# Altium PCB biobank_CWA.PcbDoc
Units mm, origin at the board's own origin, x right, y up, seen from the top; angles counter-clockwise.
Board outline 25 x 17.85 mm, 4 copper layers (Top Layer, Ground plane, MidLayer1, Bottom Layer); 54 components, 67 nets, 283 pads, 127 vias.
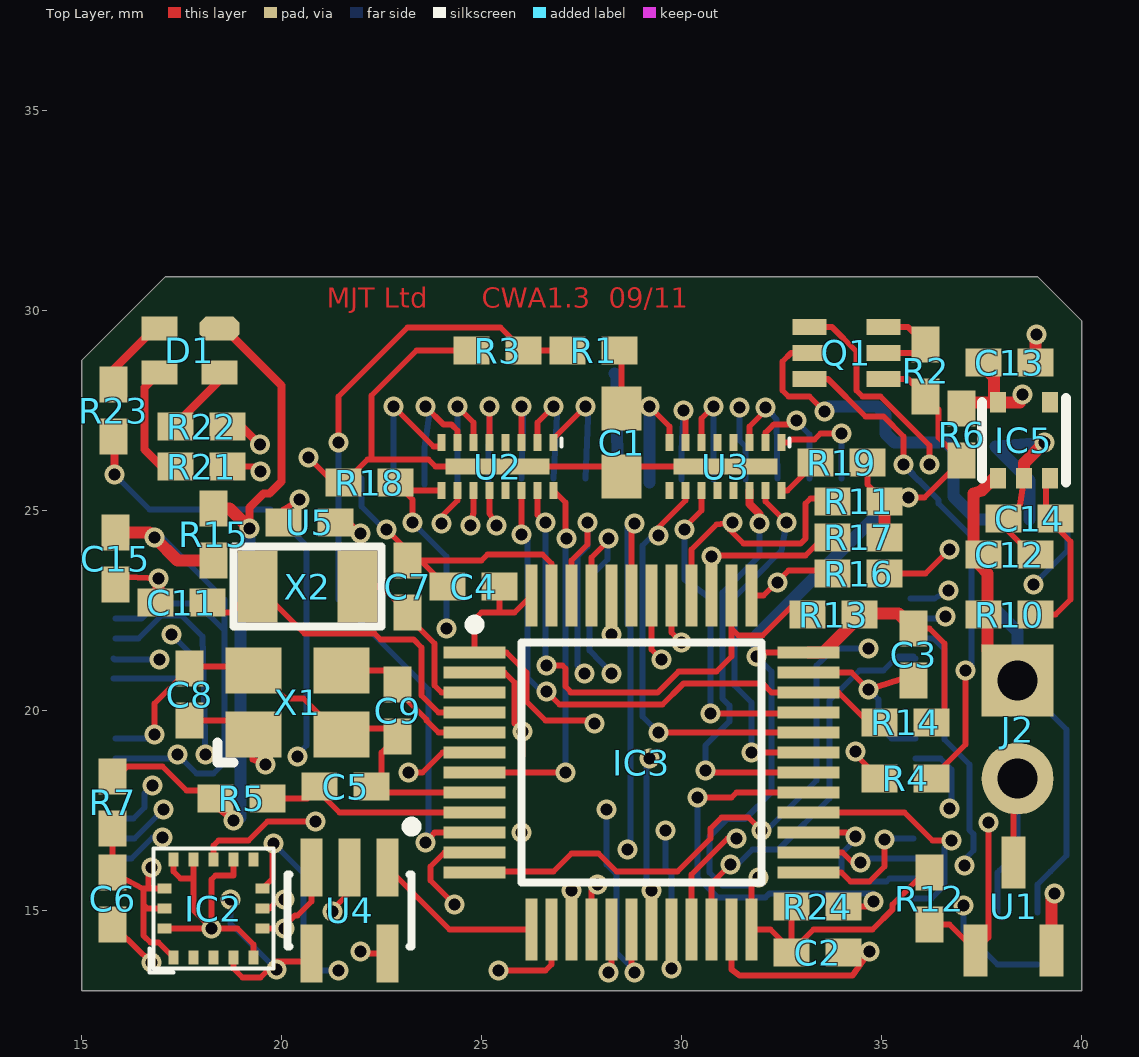
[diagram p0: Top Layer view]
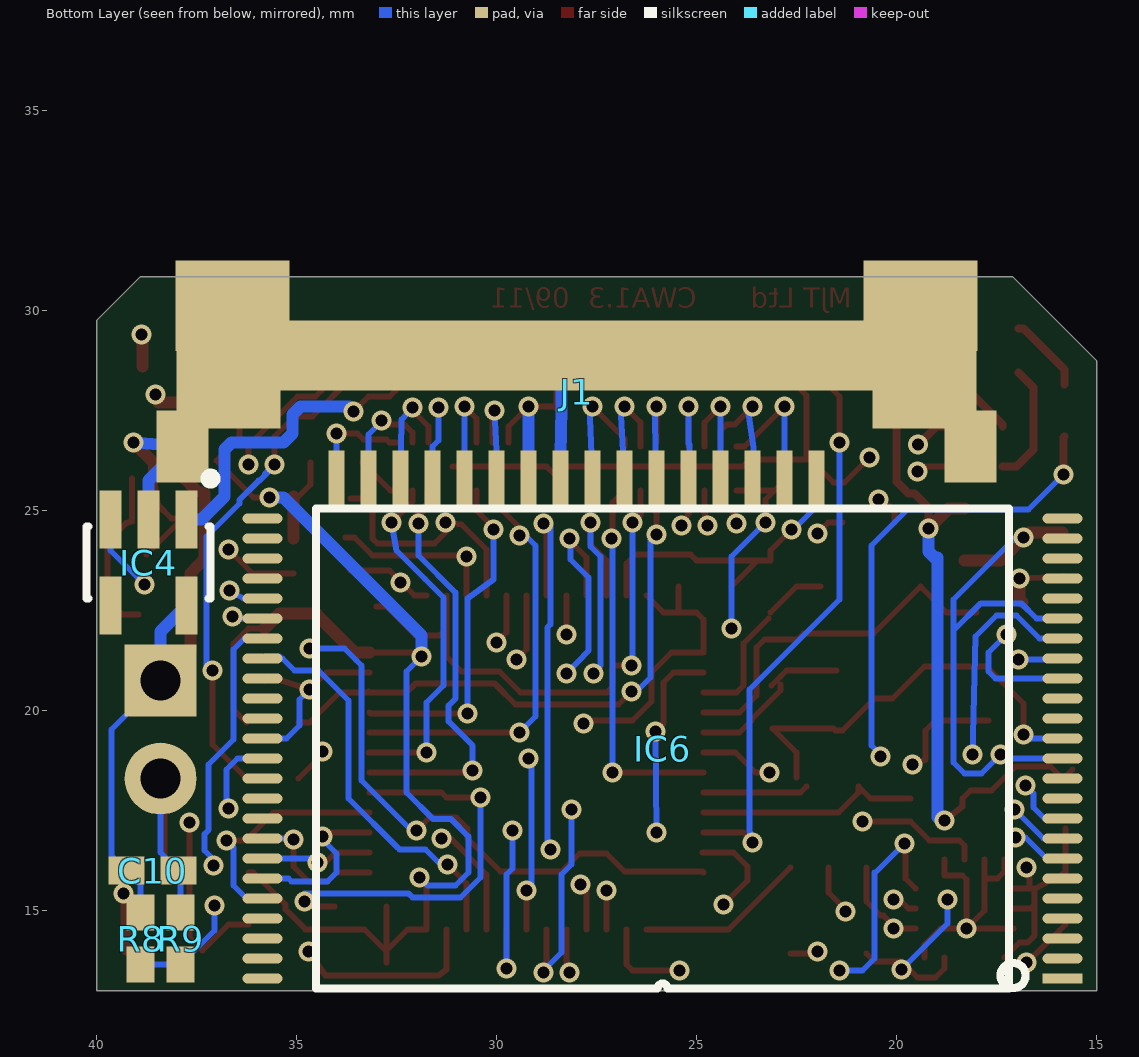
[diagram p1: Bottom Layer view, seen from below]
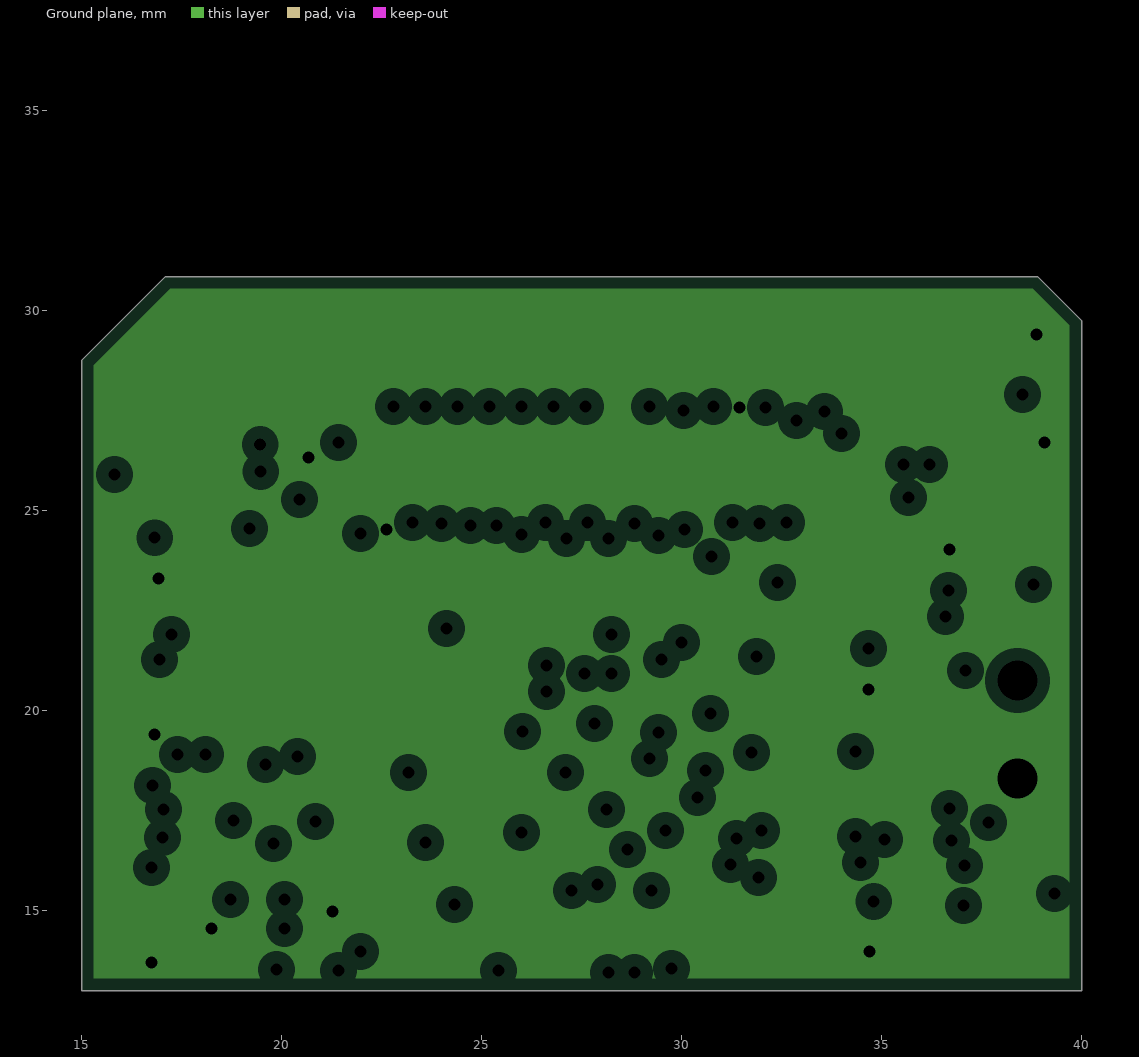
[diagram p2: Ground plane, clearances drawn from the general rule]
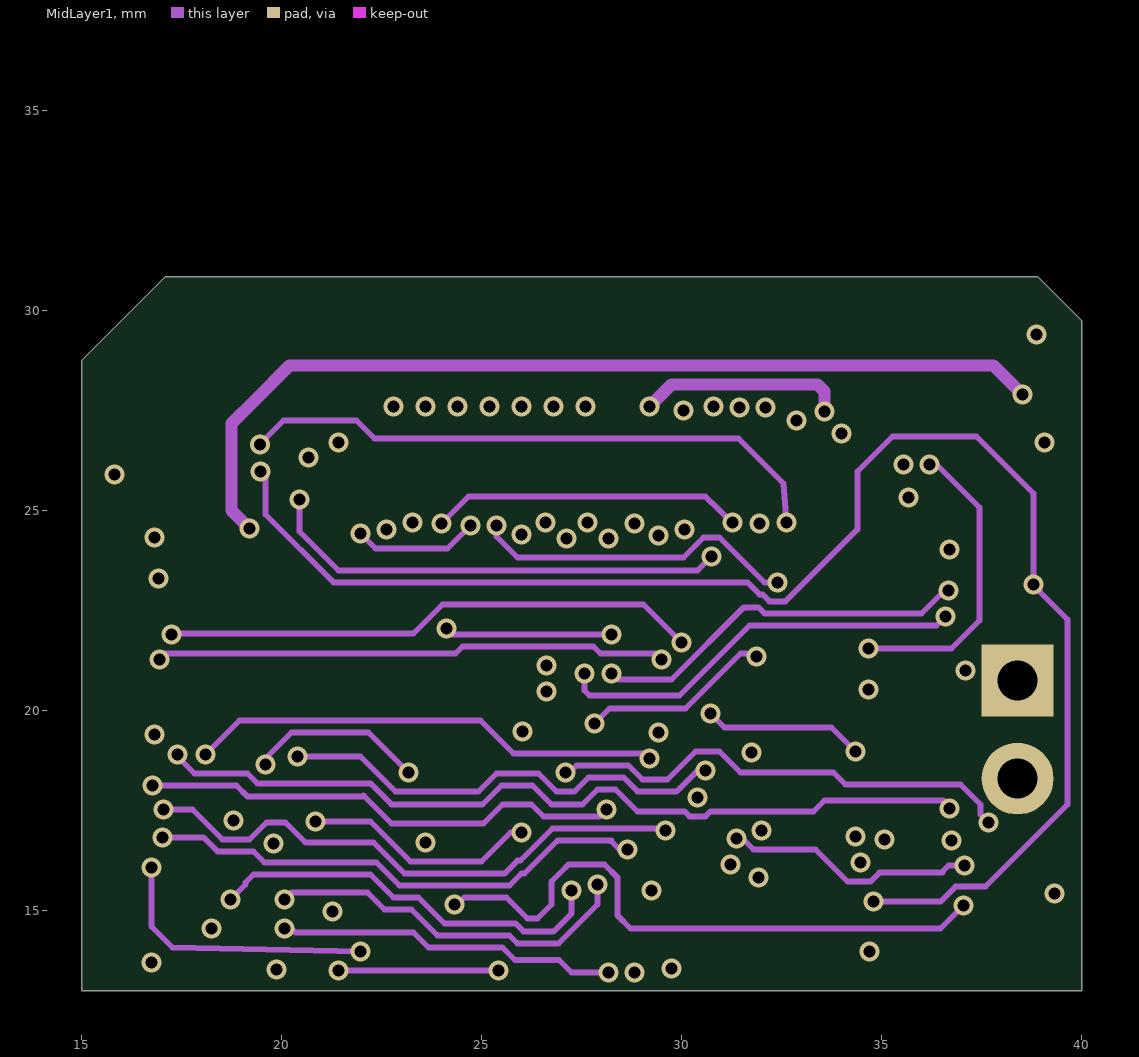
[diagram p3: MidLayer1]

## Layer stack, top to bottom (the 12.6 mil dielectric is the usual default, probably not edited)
Top Layer: signal copper 0.0356
Dielectric: core 0.32, FR-4, Dk 4.8
Ground plane: plane copper 0.0356, net GND
Dielectric: prepreg 0.32, FR-4, Dk 4.8
MidLayer1: signal copper 0.0356
Dielectric: core 0.32, FR-4, Dk 4.8
Bottom Layer: signal copper 0.0356

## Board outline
15,13 40,13 40,29.75 38.9,30.85 17.1,30.85 15,28.75

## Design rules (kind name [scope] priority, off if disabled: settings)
Clearance [All] p1: gap=0.15
ComponentClearance "Flash to socket" [(InComponent('IC6') AND InComponent('J1'))] p1: gap=-0.1 collisioncheckmode=3 verticalgap=0.254 showdistances=FALSE
ComponentClearance [All] p2: gap=0.2 collisioncheckmode=3 verticalgap=0.254 showdistances=FALSE
FabricationTestPointUsage TestPointUsage [All] p1: valid=0 allowmultiple=FALSE
FabricationTestpoint Testpoint [All] p1: side=3 testpointundercomponent=TRUE minsize=1.016 maxsize=2.54 preferedsize=1.524 minholesize=0 maxholesize=1.016 preferedholesize=0.813 testpointgrid=0.025 allowsidetop=TRUE allowsidebottom=TRUE usegrid=TRUE gridtolerance=0
PlaneClearance [All] p1: clearance=0.308
PlaneConnect [All] p1: planeconnectstyle=Relief reliefexpansion=0.508 reliefentries=4 reliefconductorwidth=0.254 reliefairgap=0.254
PolygonConnect [All] p1: connectstyle=Relief reliefconductorwidth=0.254 reliefentries=4 polygonreliefangle="90 Angle"
RoomDefinition biobank_CWA [InComponentClass('biobank_CWA')] p1: confinementstyle=ConfineIn formatcopy=TRUE lockcomponents=FALSE outline 4.75,0.5 61.75,0.5 61.75,38 4.75,38
RoutingVias [All] p1: holewidth=0.3 width=0.5 viastyle="Through Hole" minholewidth=0.3 minwidth=0.5 maxholewidth=0.3 maxwidth=0.5
SilkscreenOverComponentPads [All] p1: minsilkscreentomaskgap=0.254
SolderMaskExpansion [All] p1: expansion=0.102
Width [All] p1: maxlimit=1 minlimit=0.15 preferedwidth=0.15
22 further rules are at their usual default settings.

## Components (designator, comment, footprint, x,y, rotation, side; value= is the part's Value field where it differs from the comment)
C1 "C_0603_1u0_16V_X7R" 0603-NP 28.5,26.7 r90 top
C2 "" 0402-NP 33.4,13.95 r180 top
C3 "" 0402-NP 35.8,21.4 r90 top
C4 "" 0402-NP 24.8,23.1 r0 top
C5 "" 0402-NP 21.6,18.1 r180 top
C6 "" 0402-NP 15.775,15.3 r90 top
C7 "C_0402_4p7" 0402-NP 23.15,23.1 r270 top
C8 "C_0402_22p_NPO" 0402-NP 17.7,20.4 r270 top
C9 "C_0402_22p_NPO" 0402-NP 22.9,20 r90 top
C10 "C_0402_1u0_6V3_X5R" 0402-NP 38.6,16 r0 bottom
C11 "C_0402_4p7" 0402-NP 17.5,22.7 r0 top
C12 "" 0402-NP 38.2,23.9 r180 top
C13 "C_0402_1u0_6V3_X5R" 0402-NP 38.2,28.7 r180 top
C14 "C_0402_1u0_6V3_X5R" 0402-NP 38.7,24.8 r0 top
C15 "" 0402-NP 15.85,23.8 r90 top
D1 "" AVAGO_HSMF_C114 17.7,29 r180 top
IC2 "LIS331DLH" LGA16 18.3,15.05 r0 top
IC3 "*" F-QFP7x7-G48/N 29,18.7 r0 top
IC4 "*" SOT23-5 38.7,23.7 r0 bottom
IC5 "*" SC70 37.9,25.8 r0 top
IC6 "HY27UF084G2B-TPCB" IC_TSOPI_48_0.5MM 15.85,13.3 r0 bottom
J1 "*" HANDYLINK_16_WITH_PEGS 28,26.5 r180 bottom
J2 "CONN_2_PIN_0.1_NOOUTLINE" 2WAY_0.1_NOOUTLINE 38.4,19.5 r270 top
Q1 "FDG8842CZ" SC70-6 33.2,29.6 r270 top
R1 "" 0402-NP 27.8,29 r0 top
R2 "R_0402_10k" 0402-NP 36.1,28.5 r270 top
R3 "R_0402_220k" 0402-NP 25.4,29 r0 top
R4 "R_0402_1k5" 0402-NP 35.6,18.3 r0 top
R5 "R_0402_10R" 0402-NP 19,17.8 r180 top
R6 "R_0402_0R" 0402-NP 37,26.9 r90 top
R7 "R_0402_0R" 0402-NP 15.775,17.7 r90 top
R8 "R_0402_220k" 0402-NP 38.9,14.3 r90 bottom
R9 "" 0402-NP 37.9,14.3 r270 bottom
R10 "R_0402_10k" 0402-NP 38.2,22.4 r0 top
R11 "" 0402-NP 34.425,25.225 r0 top
R12 "" 0402-NP 36.2,15.3 r90 top
R13 "" 0402-NP 33.8,22.4 r180 top
R14 "" 0402-NP 35.6,19.7 r180 top
R15 "R_0402_0R" 0402-NP 18.3,24.4 r270 top
R16 "" 0402-NP 34.425,23.425 r180 top
R17 "" 0402-NP 34.425,24.325 r0 top
R18 "" 0402-NP 22.2,25.7 r180 top
R19 "R_0402_10k" 0402-NP 34,26.2 r0 top
R21 "R_0402_82R" 0402-NP 18,26.1 r180 top
R22 "" 0402-NP 18,27.1 r180 top
R23 "R_0402_82R" 0402-NP 15.8,27.5 r270 top
R24 "R_0402_10k" 0402-NP 33.4,15.1 r180 top
U1 "STM1001SWX6F" SOT23-3 38.3,15.1 r0 top
U2 "VEMI85AA-HGK" LLP3313-17L 25.4,26.1 r270 top
U3 "VEMI85AA-HGK" LLP3313-17L 31.1,26.1 r270 top
U4 "LM95071" SOT23-5 21.7,15 r180 top
U5 "JTAG DUMMY CORTEX M3" 0402-NP 20.7,24.7 r0 top
X1 "*" XTAL_25_32 20.4,20.2 r0 top
X2 "*" XTAL_15_32 20.65,23.1 r0 top

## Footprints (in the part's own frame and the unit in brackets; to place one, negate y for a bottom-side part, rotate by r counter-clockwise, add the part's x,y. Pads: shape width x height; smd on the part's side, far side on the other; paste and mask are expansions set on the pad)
2WAY_0.1_NOOUTLINE [mm]
  rect 1.8x1.8 hole 1: 1(-1.25,0)
  round 1.8 hole 1: 2(1.2,0)
0402-NP [mm]
  rect 0.9x0.7 smd: 1(-0.65,0) 2(0.65,0)
0603-NP [mm]
  rect 1.1x1 smd: 1(-0.85,0) 2(0.85,0)
AVAGO_HSMF_C114 [mm] "Avago HSMF-C114 multicolour LED"
  oct 1x0.6 smd: 1(-0.75,-0.55)
  rect 0.9x0.6 smd: 2(-0.75,0.55) 3(0.75,0.55) 4(0.75,-0.55)
F-QFP7x7-G48/N [mm] "QFP; 48 Leads; Body 7 x 7 mm; Pitch 0.5 mm"
  rect 1.55x0.3 smd: 1(-4.175,2.75) 2(-4.175,2.25) 3(-4.175,1.75) 4(-4.175,1.25) 5(-4.175,0.75) 6(-4.175,0.25) 7(-4.175,-0.25) 8(-4.175,-0.75) 9(-4.175,-1.25) 10(-4.175,-1.75) 11(-4.175,-2.25) 12(-4.175,-2.75) 25(4.175,-2.75) 26(4.175,-2.25) 27(4.175,-1.75) 28(4.175,-1.25) 29(4.175,-0.75) 30(4.175,-0.25) 31(4.175,0.25) 32(4.175,0.75) 33(4.175,1.25) 34(4.175,1.75) 35(4.175,2.25) 36(4.175,2.75)
  rect 0.3x1.55 smd: 13(-2.75,-4.175) 14(-2.25,-4.175) 15(-1.75,-4.175) 16(-1.25,-4.175) 17(-0.75,-4.175) 18(-0.25,-4.175) 19(0.25,-4.175) 20(0.75,-4.175) 21(1.25,-4.175) 22(1.75,-4.175) 23(2.25,-4.175) 24(2.75,-4.175) 37(2.75,4.175) 38(2.25,4.175) 39(1.75,4.175) 40(1.25,4.175) 41(0.75,4.175) 42(0.25,4.175) 43(-0.25,4.175) 44(-0.75,4.175) 45(-1.25,4.175) 46(-1.75,4.175) 47(-2.25,4.175) 48(-2.75,4.175)
  silkscreen extent -4.3,-3 3,3.57
HANDYLINK_16_WITH_PEGS [mm]
  rect 0.4x1.4 smd: 1(-6,-0.7) 2(-5.2,-0.7) 3(-4.4,-0.7) 4(-3.6,-0.7) 5(-2.8,-0.7) 6(-2,-0.7) 7(-1.2,-0.7) 8(-0.4,-0.7) 9(0.4,-0.7) 10(1.2,-0.7) 11(2,-0.7) 12(2.8,-0.7) 13(3.6,-0.7) 14(4.4,-0.7) 15(5.2,-0.7) 16(6,-0.7)
  rect 14.8x1.75 smd: PAD1(0,2.375)
  rect 2.6x2.95 smd: PAD2(-8.7,2.025) PAD4(8.7,2.025)
  rect 1.3x1.8 smd: PAD3(-9.85,0.1) PAD5(9.85,0.1)
  rect 2.85x2.26 smd: TAG1(-8.6,3.62) TAG2(8.6,3.62)
IC_TSOPI_48_0.5MM [mm]
  rect 1x0.25 smd: 1(0,0)
  oval 1x0.25 smd: 2(0,-0.5) 3(0,-1) 4(0,-1.5) 5(0,-2) 6(0,-2.5) 7(0,-3) 8(0,-3.5) 9(0,-4) 10(0,-4.5) 11(0,-5) 12(0,-5.5) 13(0,-6) 14(0,-6.5) 15(0,-7) 16(0,-7.5) 17(0,-8) 18(0,-8.5) 19(0,-9) 20(0,-9.5) 21(0,-10) 22(0,-10.5) 23(0,-11) 24(0,-11.5) 25(20,-11.5) 26(20,-11) 27(20,-10.5) 28(20,-10) 29(20,-9.5) 30(20,-9) 31(20,-8.5) 32(20,-8) 33(20,-7.5) 34(20,-7) 35(20,-6.5) 36(20,-6) 37(20,-5.5) 38(20,-5) 39(20,-4.5) 40(20,-4) 41(20,-3.5) 42(20,-3) 43(20,-2.5) 44(20,-2) 45(20,-1.5) 46(20,-1) 47(20,-0.5) 48(20,0)
  silkscreen extent 0.92,-11.75 18.66,0.25
LGA16 [mm] "LGA16 for ST Accelerometers"
  rect 0.25x0.35 smd: 1(-1,-1.225) 2(-0.5,-1.225) 3(0,-1.225) 4(0.5,-1.225) 5(1,-1.225) 9(1,1.225) 10(0.5,1.225) 11(0,1.225) 12(-0.5,1.225) 13(-1,1.225)
  rect 0.35x0.25 smd: 6(1.225,-0.5) 7(1.225,0) 8(1.225,0.5) 14(-1.225,0.5) 15(-1.225,0) 16(-1.225,-0.5)
  silkscreen extent -1.6,-1.6 1.5,1.5
LLP3313-17L [mm]
  rect 0.42x0.2 smd: 1(-0.6,1.4) 2(-0.6,1) 3(-0.6,0.6) 4(-0.6,0.2) 5(-0.6,-0.2) 6(-0.6,-0.6) 7(-0.6,-1) 8(-0.6,-1.4) 9(0.6,-1.4) 10(0.6,-1) 11(0.6,-0.6) 12(0.6,-0.2) 13(0.6,0.2) 14(0.6,0.6) 15(0.6,1) 16(0.6,1.4)
  rect 0.4x2.6 smd: 17(0,0)
  silkscreen extent -0.7,1.6 -0.5,1.6
SC70 [mm]
  rect 0.41x0.51 smd: 1(0.011,0.006) 2(0.661,0.006) 3(1.311,0.006) 4(1.311,1.906) 5(0.011,1.906)
  silkscreen extent -0.39,-0.09 1.71,2.01
SC70-6 [mm]
  rect 0.4x0.85 smd: 1(0.009,-0.005) 2(0.659,-0.005) 3(1.309,-0.005) 4(1.309,1.845) 5(0.659,1.845) 6(0.009,1.845)
SOT23-3 [mm] "SOT-23; 3 Leads; Body 3.0 x 2.6 mm, inc. leads (LxW max)"
  rect 0.6x1.3 smd: 1(-0.95,-1.1) 2(0.95,-1.1) 3(0,1.1)
SOT23-5 [mm] "SOT-23/SC-74A; 5 Leads; Body 3.1 x 3 mm, inc. leads (LxW max)"
  rect 0.55x1.45 smd: 1(-0.95,-1.075) 2(0,-1.075) 3(0.95,-1.075) 4(0.95,1.075) 5(-0.95,1.075)
  silkscreen extent -1.67,-2.22 1.55,0.9
XTAL_15_32 [mm]
  rect 1x1.8 smd: 1(-1.25,0) 2(1.25,0)
  silkscreen extent -1.85,-1 1.85,1
XTAL_25_32 [mm]
  rect 1.4x1.15 smd: 1(-1.1,-0.8) 2(1.1,-0.8) 3(1.1,0.8) 4(-1.1,0.8)
  silkscreen extent -2,-1.5 -1.6,-1

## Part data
C1 C7 C8 C9 C10 C11 C13 C14: "Capacitor"
C2 C3 C4 C5 C6 C12 C15: library part C_0402_100n_X7R, "Capacitor"
D1: library part HSMF-C114, "Avago HSMF-C114 RGB LED"
IC2: "ST digital accelerometer"
IC3: library part STM32F103C6T6, "STM32F103C6T6"
IC4: library part MAX1555EZK, "LiIon USB battery charger"
IC5: library part ZXCL280H5TA, "SC70 LDO 2.8V Regulator"
IC6: "Hynix 4Gbit NAND Flash"
J1: library part CONN_HANDYLINK_16_0.8_MOLEX_WITH_PEGS, "Molex Handylink 16 way 0.8mm"
J2: "2 pin 0.1in header"
R1 R9 R11 R12 R13 R14 R16 R17 R18: library part R_0402_100k, "Resistor"
R2 R3 R4 R5 R6 R7 R8 R10 R15 R19 R21 R23 R24: "Resistor"
R22: library part R_0402_150R, "Resistor"
U1: "Reset supervisor 2.93V open drain"
U2 U3: "8-way ESD protection"
U4: "Temperature sensor"
U5: library part JTAG_DUMMY_CORTEX_M3, "Dummy device so XJTAG is happy with number of devices in chain"
X1: library part XTAL_C3E_16MHz, "16MHz crystal 2.5x3,2mm"
X2: library part XTAL_15_32_32.768kHz_9pF, "32.768kHz 1.5x3.2mm 9pF load"

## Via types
v1: diameter 0.5, hole 0.3, Top Layer to Bottom Layer, 127 vias

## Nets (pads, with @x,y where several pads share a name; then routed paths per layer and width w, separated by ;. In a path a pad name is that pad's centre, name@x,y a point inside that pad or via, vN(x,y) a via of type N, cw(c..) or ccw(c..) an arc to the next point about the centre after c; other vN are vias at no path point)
ACC_INT: IC2.11 IC3.2 | length 14
  Top Layer w0.15: IC2.11 18.3,16.625 18.425,16.75 19.175,16.75 19.65,17.225 v1(20.85,17.225) v1@20.9,17.175 ; IC3.2 25.575,20.95 25.825,20.7 25.825,19.675 v1(26.025,19.475)
  MidLayer1 w0.15: v1(20.85,17.225) 22.225,17.225 23.225,16.225 25,16.225 25.725,16.95 v1(26,16.95)
  Bottom Layer w0.15: v1(26,16.95) v1(26.025,19.475)
BATT_SAMPLE: IC3.11 R8.1 R9.2 | length 20.7
  Top Layer w0.15: v1(24.325,15.15) 23.725,15.75 23.725,16.1 24.075,16.45 IC3.11 IC3.11@24.85,16.45
  MidLayer1 w0.15: v1(24.325,15.15) 24.4,15.15 24.575,15.325 25.625,15.325 26.15,14.8 26.4,14.8 26.75,15.15 26.75,15.726 27.124,16.1 ; 27.1,16.075 27.175,16.15 28.075,16.15 28.396,15.829 28.396,14.879 28.725,14.55 36.475,14.55 v1(37.05,15.125)
  Bottom Layer w0.15: v1(37.05,15.125) 37.05,14.5 R9.2 R8.1
BOOT0: IC3.44 R18.1 U2.9 | length 10.4
  Top Layer w0.15: R18.1@22.825,25.65 22.825,25.725 23.275,25.275 v1(23.275,24.7) ; R18.1@23.05,25.5 U2.9 ; v1(28.25,21.9) IC3.44
  MidLayer1 w0.15: v1(24.125,22.05) 24.275,21.9 v1(28.25,21.9)
  Bottom Layer w0.15: v1(23.275,24.7) 24.125,23.85 v1(24.125,22.05)
BOOT0_EXT: J1.15 U2.8 | length 3.5
  Top Layer w0.15: v1(22.8,27.6) 23.8,26.6 U2.8@24,26.6
  Bottom Layer w0.15: J1.15@22.8,25.725 22.8,26.525 v1(22.8,27.6)
CPU_TDO: IC3.39 R17.1 U5.1 | length 16.7
  Top Layer w0.15: U5.1 20.05,25.025 v1(20.45,25.275) ; IC3.39 v1(30.75,23.85) ; v1@30.75,23.7 30.925,23.875 33.1,23.875 33.55,24.325 R17.1
  MidLayer1 w0.15: v1(20.45,25.275) 20.45,24.475 21.425,23.5 30.4,23.5 v1(30.75,23.85)
D+EXT: J1.5 U3.6 | length 2.8
  Top Layer w0.15: U3.6 30.5,27.3 v1(30.8,27.6)
  Bottom Layer w0.15: J1.5@30.8,25.775 v1(30.8,27.6)
D+INT: IC3.33 R4.1 U3.11 | length 13.5
  Top Layer w0.15: v1(30.075,24.525) 30.2,24.7 30.5,25 U3.11 ; v1(30.725,19.925) 33.15,19.925 IC3.33 ; v1(34.35,18.975) 34.35,18.9 R4.1
  MidLayer1 w0.15: v1(30.725,19.925) 31.075,19.575 33.75,19.575 v1(34.35,18.975)
  Bottom Layer w0.15: v1(30.075,24.525) 30.075,23.275 30.725,22.8 v1(30.725,19.925)
D-EXT: J1.6 U3.7 | length 2.7
  Top Layer w0.15: v1(30.05,27.5) 30.1,27.5 U3.7
  Bottom Layer w0.15: J1.6@30,25.775 30,26.5 30.05,27.475 v1(30.05,27.5) v1@30,27.6
D-INT: IC3.32 U3.10 | length 10.7
  Top Layer w0.15: v1(29.425,19.45) 29.925,19.45 IC3.32 ; v1(29.425,24.375) 29.425,24.575 30.1,25.25 U3.10
  Bottom Layer w0.15: v1(29.425,19.45) 29.025,19.85 29.025,24.125 29.425,24.525 v1(29.425,24.375)
GND: C1.1 C2.1 C3.1 C4.1 C5.1 C6.1 C7.1 C8.1 C9.1 C10.1 C11.1 C12.1 C13.1 C14.1 C15.1 IC2.5 IC2.10 IC2.12 IC2.13 IC2.16 IC3.8 IC3.23 IC3.35 IC3.47 IC4.2 IC5.2 IC6.13 IC6.36 J1.4 J1.8 J1.16 J1.PAD1 J1.PAD2 J1.PAD3 J1.PAD4 J1.PAD5 J1.TAG1 J1.TAG2 J2.2 R3.1 R9.1 R16.1 R18.2 U1.3 U2.17 U3.17 U4.2 X1.2 X1.4 | length 79.5
  Top Layer w0.15: C6.1 15.925,14.5 v1(16.75,13.7) ; C15.1@15.8,23.35 15.859,23.347 v1(16.925,23.3) ; v1(16.825,19.4) 16.825,20.175 C8.1 ; IC2.16 18.9,14.55 19.3,14.15 IC2.5 ; IC2.13 17.3,15.975 17.475,15.8 17.8,15.8 ; C8.1@17.75,21.1 19.3,21.1 20.1,20.3 20.55,20.3 21.35,19.5 21.525,19.5 21.575,19.55 C9.1@23.1,19.55 ; IC2.12 17.8,15 v1(18.25,14.55) 18.25,15.775 18.35,15.875 18.775,15.875 ; 18.8,15.875 IC2.10 ; v1(20.675,26.325) 21.3,25.7 21.575,25.7 22.15,26.275 23.675,26.275 23.85,26.1 U2.17 28.25,26.1 C1.1 28.75,26.1 U3.17 ; v1@21.225,14.975 21.7,15.45 U4.2 ; C5.1 22.4,17.95 IC3.8 ; 22.25,26.275 22.25,27.875 23.375,29 R3.1 ; C5.1@22.5,18.325 22.5,18.95 C9.1@23.1,19.55 ; v1@22.625,24.625 v1(22.625,24.525) 23.15,24 C7.1 C7.1@23.475,23.75 ; C9.1@22.9,19.55 C9.1@23.1,19.55 ; C4.1@24.125,23.1 C7.1@23.475,23.75 ; IC3.47 26.75,23.675 26.525,23.9 25.15,23.9 25,23.75 C7.1@23.475,23.75 ; IC3.23 31.25,13.525 31.45,13.375 34.275,13.375 v1(34.7,13.975) ; IC3.35 34.25,20.95 v1(34.675,20.525) 35.7,20.85 C3.1 ; R16.1 36.1,23.425 v1(36.7,24.025) ; U1.3 38.3,18.2 J2.2@38.375,18.275 ; IC5.2@38.561,25.781 38.461,25.136 38.125,24.8 37.85,24.8 C12.1@38.75,23.9
  Top Layer w0.3: C11.1 16.925,22.775 v1(16.925,23.3) ; IC5.2 38.561,26.186 v1(39.075,26.7) ; C13.1@38.85,28.6 38.85,29.375 v1(38.875,29.4)
  Bottom Layer w0.15: IC6.13 16.725,19.3 v1(16.825,19.4) ; J1.16 22,25.1 22.575,24.525 v1(22.625,24.525) ; v1(31.45,27.575) 31.454,27.576 v1@31.6,27.6 ; v1@31.45,27.6 31.45,26.75 31.6,26.6 J1.4@31.6,25.775 ; v1(34.675,20.525) 34.925,20.275 34.925,19.625 35.25,19.3 IC6.36 ; R9.1 37.9,15.95 C10.1 38.4,16.45 J2.2
  Bottom Layer w0.3: J1.PAD1@28.325,28.425 28.375,28.375 28.375,27.55 28.4,26.4 J1.8@28.4,25.675 ; J1.PAD1@28.4,28.925 J1.PAD1@28.425,28.95 ; IC4.2 38.7,25.75 J1.PAD3 v1(39.075,26.7)
  other v1: 21.275,14.975
LED_B_TXD: IC3.30 R23.2 U3.14 | length 33.7
  Top Layer w0.15: v1(30.6,18.5) 30.65,18.45 IC3.30
  Top Layer w0.2: R23.2 15.825,26.825 v1(15.825,25.9) ; U3.14 31.7,25.165 31.952,24.914 v1(31.952,24.676)
  MidLayer1 w0.15: v1(20.4,18.85) 21.975,18.85 22.85,17.975 24.925,17.975 25.375,18.425 26.425,18.425 26.875,17.975 27.325,17.975 27.675,18.325 28.551,18.325 28.901,17.975 29.878,17.975 30.403,18.5 v1(30.6,18.5)
  Bottom Layer w0.15: v1(15.825,25.9) 16.7,25.025 19.725,25.025 20.625,24.125 20.625,19.125 v1@20.4,18.9 ; v1(30.6,18.5) 30.6,19.128 31.2,19.728 31.2,20.122 31.025,20.297 31.025,22.949 31.952,23.876 v1(31.952,24.676)
  Bottom Layer w0.2: v1(31.952,24.676) v1@31.974,24.676
LED_G_NCHG: IC3.29 IC4.3 R21.1 R24.1 | length 52.5
  Top Layer w0.15: R21.1 19.352,26.1 v1(19.476,25.976) ; v1(30.4,17.825) 31.25,17.825 31.375,17.95 IC3.29 ; R24.1 34.676,15.1 v1(34.802,15.226)
  MidLayer1 w0.15: v1(19.476,25.976) 19.599,25.976 19.599,24.902 21.301,23.2 31.651,23.2 31.951,22.9 32.028,22.9 32.203,22.725 32.597,22.725 34.4,24.528 34.4,25.975 35.275,26.85 37.375,26.85 38.8,25.425 v1(38.8,23.15) 38.8,23.125 39.65,22.275 39.65,17.65 37.6,15.6 36.853,15.6 36.479,15.226 v1(34.802,15.226)
  Bottom Layer w0.15: v1(30.4,17.825) 30.4,15.826 30.901,15.325 32.097,15.325 32.195,15.423 34.802,15.423 v1(34.802,15.226) ; v1(38.8,23.15) 39.65,24 IC4.3 IC4.3@39.65,24.075
LED_R_RXD: IC3.31 R22.1 U3.15 | length 24.9
  Top Layer w0.15: v1(31.75,18.95) IC3.31@33.2,18.95 ; U3.15 32.1,25.225 32.575,24.75 v1(32.625,24.7)
  Top Layer w0.2: R22.1 19,27.1 19.45,26.65 v1(19.466,26.65)
  MidLayer1 w0.15: v1(19.466,26.65) 19.45,26.65 20.05,27.25 21.875,27.25 22.325,26.8 31.425,26.8 32.55,25.675 v1(32.625,24.7)
  Bottom Layer w0.15: v1(31.75,18.95) 31.75,20.2 31.325,20.625 31.325,22.825 31.788,23.288 32.5,24 v1(32.625,24.7)
NAND_ALE: IC3.42 IC6.17 | length 15.8
  Top Layer w0.15: IC3.42 29.25,21.525 v1(29.5,21.275)
  MidLayer1 w0.15: v1(16.95,21.275) 16.925,21.425 24.35,21.425 24.525,21.6 27.8,21.6 27.975,21.425 29.35,21.425 v1(29.5,21.275)
  Bottom Layer w0.15: IC6.17@15.8,21.3 15.825,21.275 v1(16.95,21.275)
NAND_CLE: IC3.41 IC6.16 | length 17.8
  Top Layer w0.15: IC3.41 29.75,21.95 v1(30,21.7)
  MidLayer1 w0.15: v1(17.25,21.9) 17.275,21.925 23.3,21.925 24.025,22.65 29.05,22.65 v1(30,21.7)
  Bottom Layer w0.15: IC6.16@15.8,20.8 17.525,20.8 17.7,20.975 17.7,21.45 v1(17.25,21.9)
NAND_D0: IC3.45 IC6.29 | length 16
  Top Layer w0.15: IC3.45 27.75,23.826 v1@28.175,24.251
  MidLayer1 w0.15: v1@28.262,20.938 28.425,20.775 29.75,20.775 31.556,22.581 31.923,22.581 32.079,22.425 36,22.425 v1@36.725,23.15
  Bottom Layer w0.15: v1@28.15,24.275 28.15,23.775 27.7,23.325 27.7,21.5 v1(28.25,20.925) ; IC6.29@35.725,22.8 36.325,22.8 v1(36.675,23)
  other v1: 28.175,24.3
NAND_D1: IC3.46 IC6.30 | length 17.4
  Top Layer w0.15: IC3.46 27.25,23.75 27.65,24.15 v1(27.65,24.7)
  MidLayer1 w0.15: v1(27.575,20.925) 27.575,20.5 27.7,20.375 29.95,20.375 31.7,22.125 36.375,22.125 v1@36.531,22.281 ; v1@36.481,22.331 36.5,22.35 v1(36.6,22.35)
  Bottom Layer w0.15: v1(27.575,20.925) 27.4,21.125 27.4,23.85 27.65,24.1 v1(27.65,24.7) ; IC6.30@35.8,22.3 36.75,22.3 v1(36.6,22.35)
NAND_D2: IC3.21 IC6.31 | length 15.9
  Top Layer w0.15: IC3.21 30.25,15.901 31.149,16.8 v1(31.375,16.8)
  MidLayer1 w0.15: v1(31.375,16.8) 31.525,16.8 31.8,16.525 33.35,16.525 34.15,15.725 34.726,15.725 34.951,15.95 36.525,15.95 ; 36.5,15.95 36.675,16.125 v1(37.075,16.125)
  Bottom Layer w0.15: IC6.31@35.8,21.8 36.3,21.8 36.575,21.525 36.575,19.275 37.2,18.65 37.2,17.008 37.3,16.908 37.3,16.5 37.075,16.275 v1(37.075,16.125)
NAND_D3: IC3.22 IC6.32 | length 10.4
  Top Layer w0.15: IC3.22 30.75,15.675 v1(31.225,16.15)
  Bottom Layer w0.15: v1(31.225,16.15) 31.4,16.15 31.775,16.525 32.425,16.525 ; 32.425,16.525 32.482,16.582 33.7,17.8 33.7,20.25 34.45,21 35.05,21 35.35,21.3 IC6.32 ; IC6.32@35.425,21.35 IC6.32@35.8,21.35
NAND_D4: IC3.25 IC6.41 | length 3.9
  Top Layer w0.15: IC3.25 34,15.95 34.225,15.725 34.7,15.725 35.075,16.1 v1(35.075,16.775)
  Bottom Layer w0.15: v1(35.075,16.775) 34.925,16.8 IC6.41@35.8,16.8
NAND_D5: IC3.26 IC6.42 | length 2.8
  Top Layer w0.15: IC3.26 34.025,16.45 34.275,16.2 v1(34.475,16.2)
  Bottom Layer w0.15: v1(34.475,16.2) 34.575,16.3 IC6.42
NAND_D6: IC3.27 IC6.43 | length 4.2
  Top Layer w0.15: IC3.27@33.2,16.95 IC3.27 34.125,16.95 v1(34.35,16.85)
  Bottom Layer w0.15: v1(34.35,16.85) 34.35,16.775 34,16.425 34,15.95 34.225,15.725 35.125,15.725 35.2,15.8 IC6.43
NAND_D7: IC3.28 IC6.44 | length 6
  Top Layer w0.15: IC3.28 35.575,17.45 36.275,16.75 v1(36.75,16.75)
  Bottom Layer w0.15: IC6.44@35.8,15.3 36.25,15.3 36.575,15.625 36.575,16.575 v1(36.75,16.75)
NAND_NCE: IC3.18 IC6.9 | length 18.8
  Top Layer w0.15: v1@28.75,13.575 IC3.18
  MidLayer1 w0.15: v1(16.775,18.125) 18.875,18.125 19.143,17.857 22.068,17.857 ; 22.05,17.875 22.75,17.175 25.05,17.175 25.525,17.65 26.25,17.65 26.55,17.35 27.95,17.35 v1(28.125,17.525)
  Bottom Layer w0.15: IC6.9 16.3,17.3 16.575,17.575 16.575,17.925 v1(16.775,18.125) ; v1@28.125,17.475 28.125,16.15 28.375,15.9 28.375,13.95 v1@28.825,13.5
  other v1: 28.825,13.45
NAND_NRE: IC3.20 IC6.8 | length 20.1
  Top Layer w0.15: v1(29.75,13.55) IC3.20
  MidLayer1 w0.15: v1(17.05,17.525) 17.775,17.525 18.525,16.775 19.2,16.775 19.625,17.2 20.1,17.2 20.6,16.7 22.3,16.7 23.075,15.925 25.576,15.925 25.901,16.25 25.974,16.25 26.774,17.05 v1@29.6,17.05
  Bottom Layer w0.15: IC6.8 16.325,16.8 v1(17.05,17.525) ; v1@29.6,17.05 29.6,16.05 29.75,15.9 v1(29.75,13.55)
  other v1: 29.6,17
NAND_NWE: IC3.19 IC6.18 | length 21.9
  Top Layer w0.15: IC3.19 v1(29.25,15.5)
  MidLayer1 w0.15: v1(18.1,18.9) 18.95,19.75 24.975,19.75 25.8,18.925 29.075,18.925 v1(29.2,18.8)
  Bottom Layer w0.15: IC6.18 16.425,21.8 17,22.375 17.5,22.375 18.025,21.85 v1(18.1,18.9) ; v1(29.25,15.5) 29.125,15.625 29.125,18.725 v1(29.2,18.8) 29.25,18.825 v1@29.25,18.8
NAND_RNB: IC3.43 IC6.7 | length 24.2
  Top Layer w0.15: IC3.43 v1@28.75,24.675
  MidLayer1 w0.15: v1(17.025,16.825) 18.051,16.825 18.401,16.475 19.3,16.475 19.575,16.2 22.375,16.2 22.95,15.625 25.7,15.625 26,15.925 26.073,15.925 26.898,16.75 28.25,16.75 28.25,16.725 28.45,16.525 v1(28.65,16.525)
  Bottom Layer w0.15: IC6.7 16.25,16.3 16.775,16.825 v1(17.025,16.825) ; v1(28.65,16.525) 28.725,16.6 28.725,22.081 28.65,22.156 28.65,24.6 v1(28.825,24.675)
NetC14_2: C14.2 IC5.3 R10.2 | length 4.2
  Top Layer w0.15: R10.2@38.95,22.4 39.35,22.4 39.725,22.775 39.725,24.225 39.261,24.689 C14.2@39.111,24.725 ; C14.2@39.111,24.8 IC5.3@39.111,25.806
NetD1_2: D1.2 R22.2 | length 1.8
  Top Layer w0.2: R22.2 17.35,27.15 18.45,28.25 D1.2
NetD1_3: D1.3 R21.2 | length 3
  Top Layer w0.2: D1.3 16.575,28.075 16.575,26.525 17,26.1 R21.2
NetD1_4: D1.4 R23.1 | length 1.9
  Top Layer w0.2: R23.1 15.8,28.525 16.825,29.55 D1.4
NetQ1_3: Q1.3 R4.2 | length 12.7
  Top Layer w0.15: Q1.3 33.659,28.291 34.6,27.35 35.051,27.35 35.55,26.851 v1(35.55,26.15) ; R4.2 37.1,19.15 v1(37.1,21)
  Bottom Layer w0.15: v1(35.55,26.15) 35.79,25.91 35.79,25.885 ; 35.714,25.961 35.926,25.749 35.946,25.749 36.425,25.269 36.425,25.175 37.25,24.35 37.25,21.15 v1(37.1,21)
NetQ1_5: Q1.5 Q1.6 R2.1 | length 2.7
  Top Layer w0.15: Q1.5 35.891,28.941 R2.1 ; Q1.6 35.659,29.591 R2.1 ; R2.1@35.859,29.391 R2.1
NetR19_1: R19.1 U3.16 | length 1.1
  Top Layer w0.15: U3.16 32.65,25.5 R19.1
NRST: IC3.7 R12.1 U1.1 U2.16 | length 26.2
  Top Layer w0.15: IC3.7 v1(27.1,18.45) ; U2.16 27.1,25.2 v1@27.1,24.3 ; R12.1 36.7,14.65 U1.1 37.675,14.325 v1(37.675,17.2)
  MidLayer1 w0.15: v1(27.1,18.45) 27.2,18.45 27.375,18.625 28.675,18.625 29.025,18.275 29.65,18.275 30.35,18.975 30.95,18.975 31.475,18.45 33.8,18.45 34.1,18.15 36.975,18.15 37.475,17.65 37.475,17.4 v1(37.675,17.2)
  Bottom Layer w0.15: v1(27.1,18.45) v1@27.1,24.3
  other v1: 27.125,24.3
NRST_EXT: J1.9 U2.1 | length 3.2
  Top Layer w0.15: U2.1@26.8,26.6 26.8,26.8 v1(27.6,27.6)
  Bottom Layer w0.15: J1.9 27.675,27.6 v1(27.6,27.6)
NUSB_PULLUP: IC3.12 Q1.1 | length 27.5
  Top Layer w0.15: IC3.12 24.85,15.975 26.8,15.975 27.25,16.425 27.925,16.425 28.375,15.975 29.9,15.975 30.725,16.8 30.725,17.05 31,17.325 31.675,17.325 v1(32,17) ; Q1.1 33.759,29.591 34.375,28.975 34.375,28 34.525,27.85 34.975,27.85 36.2,26.625 v1(36.2,26.15)
  MidLayer1 w0.15: v1(34.675,21.55) 36.75,21.55 37.45,22.25 37.45,25.075 36.375,26.15 v1(36.2,26.15)
  Bottom Layer w0.15: v1(32,17) 32.125,17 33.375,18.25 33.375,21.125 33.513,21.263 33.8,21.55 v1(34.675,21.55)
OSC32_IN: C7.2 IC3.3 X2.2 | length 4.5
  Top Layer w0.15: X2.2 22.5,23.1 C7.2 ; C7.2@23.2,22.3 23.825,21.675 23.825,20.625 24,20.45 IC3.3
OSC32_OUT: C11.2 IC3.4 X2.1 | length 9.1
  Top Layer w0.15: C11.2@18,22.45 18.75,22.45 X2.1 20.575,21.925 22.325,21.925 22.475,21.775 23.301,21.775 23.5,21.576 23.5,20.375 23.925,19.95 IC3.4
OSC_IN: C9.2 IC3.5 X1.3 | length 4.3
  Top Layer w0.15: X1.3 22.75,21 22.9,20.85 C9.2@23.125,20.625 ; C9.2 22.9,20.5 23.625,19.775 23.625,19.75 23.925,19.45 IC3.5
OSC_OUT: C8.2 IC3.6 X1.1 | length 9
  Top Layer w0.15: C8.2 19.025,19.75 19.275,19.5 19.275,18.775 v1(19.6,18.65) ; v1(23.175,18.45) 23.525,18.45 24.025,18.95 IC3.6
  MidLayer1 w0.15: v1(19.6,18.65) 19.6,18.8 20.25,19.45 22.175,19.45 v1(23.175,18.45)
RXD_EXT: J1.2 U3.2 | length 2.5
  Top Layer w0.15: U3.2 32.1,26.951 32.289,27.139 ; 32.312,27.15 v1@32.7,27.15
  Bottom Layer w0.15: v1(32.875,27.25) 32.925,27.175 33.2,26.9 J1.2
SPI_MISO: IC2.7 IC3.16 | length 11.3
  Top Layer w0.15: IC2.7 19.7,15.05 19.925,15.275 v1(20.075,15.275) ; IC3.16 27.75,15.5 v1(27.9,15.65)
  MidLayer1 w0.15: v1@19.925,15.275 v1(20.075,15.275) 20.25,15.45 22.15,15.45 22.575,15.025 23.25,15.025 23.9,14.375 25.7,14.375 25.9,14.175 26.925,14.175 27.9,15.15 v1(27.9,15.65)
SPI_MOSI: IC2.6 IC3.17 U4.3 | length 12.2
  Top Layer w0.15: IC2.6 v1(20.075,14.55) 20.075,14.619 20.331,14.875 20.4,14.875 20.75,15.225 U4.3 ; v1@28.1,13.4 28.25,13.55 IC3.17
  MidLayer1 w0.15: v1@20.075,14.575 v1(20.075,14.55) 20.25,14.55 20.35,14.45 23.3,14.45 23.675,14.075 25.525,14.075 25.837,13.763 26.937,13.763 27.25,13.45 v1(28.175,13.45)
SPI_NSS: IC2.8 IC3.14 | length 11.7
  Top Layer w0.15: IC2.8 19.775,15.8 v1@19.775,16.7 ; v1(25.425,13.5) 26.6,13.5 26.75,13.65 IC3.14
  MidLayer1 w0.15: v1(21.425,13.5) v1(25.425,13.5)
  Bottom Layer w0.15: v1(19.8,16.675) 20.55,15.925 ; 20.55,15.95 20.55,13.8 20.85,13.5 v1(21.425,13.5)
SPI_SCK: IC2.4 IC3.15 U4.4 | length 15.9
  Top Layer w0.15: IC2.4 18.8,13.55 19.025,13.325 19.475,13.325 19.875,13.725 20.55,13.725 U4.4 ; IC3.15@27.25,14.525 v1(27.25,15.5)
  MidLayer1 w0.15: v1(18.725,15.275) 19.1,15.65 ; 19.1,15.7 19.3,15.9 22.225,15.9 22.8,15.325 23.425,15.325 24.075,14.675 25.851,14.675 26.051,14.475 26.801,14.475 27.25,14.924 v1(27.25,15.5)
  Bottom Layer w0.15: v1(18.725,15.275) 18.725,14.675 v1(19.875,13.525)
TCK: IC3.37 R16.2 U2.12 | length 11.3
  Top Layer w0.15: U2.12 25.2,24.925 v1(25.375,24.625) ; IC3.37 32.05,22.875 32.675,23.5 R16.2@33.65,23.5
  MidLayer1 w0.15: v1(25.375,24.625) 25.375,24.35 25.9,23.825 30.05,23.825 30.55,24.325 30.95,24.325 32.075,23.2 v1(32.4,23.2)
TCK_EXT: J1.12 U2.5 | length 2.9
  Top Layer w0.15: U2.5@25.2,26.6 v1(25.2,27.6)
  Bottom Layer w0.15: J1.12@25.175,25.725 25.175,26.65 25.2,26.675 v1(25.2,27.6)
TDI: IC3.38 R13.2 U2.15 | length 13.9
  Top Layer w0.15: U2.15 26.4,24.892 v1(26.6,24.7) ; v1(26.625,21.125) 27.025,21.125 27.1,21.05 27.1,20.6 27.25,20.45 ; 27.225,20.45 29.401,20.45 29.926,20.975 30.875,20.975 31.25,21.35 IC3.38 ; 31.25,22.05 31.425,21.875 32.025,21.875 32.75,22.6 R13.2@33,22.6
  Bottom Layer w0.15: v1(26.6,24.7) 26.6,21.025 v1(26.625,21.125)
TDI_EXT: J1.10 U2.2 | length 3.2
  Top Layer w0.15: U2.2@26.4,26.6 26.4,27.2 v1(26.8,27.6) v1@26.7,27.6
  Bottom Layer w0.15: J1.10 26.9,27.6 v1(26.8,27.6)
TDO: U2.11 U5.2 | length 4.8
  Top Layer w0.15: U5.2 21.7,24.7 v1(21.975,24.425) ; v1(24.725,24.625) 24.8,24.95 U2.11
  MidLayer1 w0.15: v1(21.975,24.425) 22.35,24.05 24.15,24.05 v1(24.725,24.625)
TDO_EXT: J1.13 U2.6 | length 3.3
  Top Layer w0.15: v1@24.5,27.6 v1(24.4,27.6) 24.8,27.2 U2.6@24.8,26.6
  Bottom Layer w0.15: J1.13@24.4,25.525 24.4,26.275 24.4,27.575 v1(24.4,27.6)
TEMP_NCS: IC3.13 U4.1 | length 4.2
  Top Layer w0.15: U4.1 24.2,14.525 IC3.13
TMS: IC3.34 R14.2 U2.14 | length 14.5
  Top Layer w0.15: v1(26,24.4) 26,24.625 U2.14 ; v1(26.625,20.475) 26.95,20.15 29.525,20.15 30.016,20.641 30.045,20.67 32.03,20.67 32.25,20.45 IC3.34 ; IC3.34@33.2,20.475 IC3.34 ; R14.2 34.675,19.7 33.925,20.45 IC3.34
  Bottom Layer w0.15: v1(26,24.4) 26.15,24.275 26.15,20.825 26.5,20.475 v1(26.625,20.475)
TMS_EXT: J1.11 U2.3 | length 2.8
  Top Layer w0.15: U2.3 v1(26,27.6)
  Bottom Layer w0.15: J1.11 26.05,27.6 v1(26,27.6)
TRST: IC3.40 R11.1 U2.10 | length 15
  Top Layer w0.15: v1(24,24.675) 24,24.85 24.4,25.25 U2.10 ; IC3.40 30.25,24.025 30.875,24.65 v1(31.275,24.7) 31.2,24.525 31.55,24.175 32.976,24.175 33.1,24.299 33.1,25.175 33.225,25.3 R11.1@33.65,25.3
  MidLayer1 w0.15: v1(24,24.675) 24.675,25.35 30.6,25.35 v1(31.275,24.7)
TRST_EXT: J1.14 U2.7 | length 3.6
  Top Layer w0.15: v1@23.7,27.6 v1(23.6,27.6) 24.051,27.149 24.251,27.149 24.4,27 U2.7@24.4,26.6
  Bottom Layer w0.15: J1.14@23.575,25.65 23.575,26.575 23.725,27.6 v1(23.6,27.6)
TXD_EXT: J1.3 U3.3 | length 2.9
  Top Layer w0.15: U3.3 31.7,27.1 32.1,27.5 v1(32.1,27.575)
  Bottom Layer w0.15: v1(32.1,27.575) 32.375,27.275 J1.3
V_BATT: C10.2 C12.2 IC4.5 IC5.1 J2.1 R8.2 R10.1 U1.2 | length 16
  Top Layer w0.3: IC5.1@37.811,25.806 37.505,25.5 37.3,25.425 37.3,23.8 37.65,23.425 37.65,23.4 37.65,21.5 J2.1 ; U1.2@39.25,14.025 39.25,15.35 v1(39.325,15.425)
  Bottom Layer w0.15: J2.1 39.625,19.525 39.625,16.375 39.225,15.975 38.9,15.65 R8.2
  Bottom Layer w0.3: IC4.5 38.4,21.975 J2.1
V_BUS: C1.2 IC4.1 J1.7 Q1.2 R1.2 U3.8 | length 19.4
  Top Layer w0.15: R1.2@28.5,28.95 C1.2 28.55,27.6 v1(29.2,27.6) 29.7,27.1 U3.8 ; Q1.2 32.741,28.941 32.525,28.725 32.525,28 32.675,27.85 33.2,27.85 v1(33.575,27.475)
  MidLayer1 w0.3: v1(29.2,27.6) 29.75,28.15 33.4,28.15 33.575,27.975 v1(33.575,27.475)
  Bottom Layer w0.3: J1.7@29.2,25.7 29.2,26.35 29.2,27.45 v1(29.2,27.6) ; v1(33.575,27.475) 33.575,27.5 33.675,27.6 34.9,27.6 35.1,27.4 35.1,26.925 35.325,26.7 36.625,26.7 36.8,26.525 36.8,25.35 37.375,24.775 IC4.1
VBUS_DET: IC3.10 R1.1 R3.2 | length 20.1
  Top Layer w0.15: v1(21.425,26.7) 21.425,27.85 23.15,29.575 25.475,29.575 R3.2 R1.1 ; v1(23.6,16.7) 23.825,16.95 IC3.10
  Bottom Layer w0.15: v1(21.425,26.7) 21.425,22.775 23.675,20.525 23.675,17 v1(23.6,16.7)
VDD_2V8: C13.2 D1.1 IC5.5 R5.2 R6.2 R7.2 R15.1 | length 45
  Top Layer w0.15: R7.2@15.6,18.525 R7.2 15.9,18.35 16.15,18.6 17.025,18.6 17.625,18 18.15,18 R5.2 18.35,17.6 v1(18.8,17.25)
  Top Layer w0.2: D1.1 18.575,29.55 20,28.125 20,25.725 19.7,25.425 19.55,25.425 19.2,25.075 v1(19.2,24.55)
  Top Layer w0.3: R15.1 18.7,25.05 v1(19.2,24.55) ; R6.2 37.156,27.706 37.811,27.706 37.811,28.339 C13.2@37.55,28.6 ; IC5.5 38.456,27.706 v1(38.525,27.9)
  MidLayer1 w0.3: v1(19.2,24.55) 18.75,25 18.75,27.175 19.352,27.777 20.2,28.625 37.8,28.625 v1(38.525,27.9)
  Bottom Layer w0.3: v1(18.8,17.25) 18.975,17.325 18.975,23.825 ; 18.975,23.75 19.2,23.975 v1(19.2,24.55)
VDD_A: C5.2 IC3.9 R5.1 | length 5.7
  Top Layer w0.15: R5.1 20.65,17.8 C5.2 20.95,17.95 21.45,17.45 IC3.9
VDD_ACC: C6.2 IC2.1 IC2.14 IC2.15 R7.1 U4.5 | length 13.6
  Top Layer w0.15: R7.1 C6.2 ; C6.2@15.95,15.775 C6.2 ; 16.55,15.15 16.65,15.05 IC2.15 ; 16.55,15.55 16.55,14.375 16.725,14.2 16.925,14.2 IC2.1 ; 16.675,15.55 16.675,16 v1(16.75,16.075) ; IC2.14 16.525,15.55 C6.2 ; v1(21.975,13.975) 22.125,13.925 U4.5
  MidLayer1 w0.15: v1(16.75,16.075) 16.75,14.6 17.275,14.075 v1(21.975,13.975)
VDD_CPU: C2.2 C3.2 C4.2 IC3.1 IC3.24 IC3.36 IC3.48 Q1.4 R2.2 R6.1 R11.2 R12.2 R13.1 R14.1 R17.2 R19.2 R24.2 | length 50.1
  Top Layer w0.15: 25.45,22.45 C4.2 ; IC3.48 25.825,22.45 25,22.45 24.825,22.275 IC3.1 25.625,21.45 26.125,20.95 26.125,20.225 26.6,19.75 27.75,19.75 v1(27.825,19.675) ; v1(31.875,21.35) 31.975,21.45 IC3.36 ; v1(31.925,15.825) 31.75,15.65 IC3.24 32.225,14.525 32.75,14 R24.2 ; C2.2@32.75,13.7 32.75,13.975 33.3,14.525 34.773,14.525 35.277,15.029 35.277,15.152 36.075,15.95 R12.2 ; IC3.36@33.5,21.45 R13.1 R13.1@34.5,22.4 ; R19.2 34.65,25.65 R11.2 ; Q1.4 35.659,28.291 36.425,27.525 36.425,26.825 R6.1 36.075,25.325 v1(35.675,25.325) ; C3.2 36.2,22.05 36.575,21.675 36.575,20.025 R14.1
  Top Layer w0.3: IC3.36 33.55,21.45 R13.1@34.5,22.4 ; R13.1@34.5,22.425 35.425,22.425 C3.2 ; R17.2@35.075,24.3 R17.2 R11.2 R11.2@35.075,25.35
  MidLayer1 w0.15: v1(27.825,19.675) 28.2,20.05 30.1,20.05 31.475,21.425 31.625,21.425 31.7,21.35 v1(31.875,21.35)
  Bottom Layer w0.15: v1(31.875,21.35) 32.25,20.975 32.25,17.95 31.583,17.283 31.135,17.283 30.7,16.848 30.7,15.95 31.025,15.625 31.725,15.625 v1(31.925,15.825)
  Bottom Layer w0.3: v1(31.875,21.35) 31.875,21.875 35.325,25.325 v1(35.675,25.325)
VDD_CPU_EXT: J1.1 U3.1 | length 2.7
  Top Layer w0.15: U3.1 32.675,26.7 32.75,26.775 33.325,26.775 33.475,26.925 v1(34,26.925)
  Bottom Layer w0.15: J1.1 v1(34,26.925)
VDD_NAND: C15.2 IC6.12 IC6.19 IC6.37 R15.2 | length 38.4
  Top Layer w0.3: C15.2 16.7,24.45 v1(16.828,24.322) 17.4,23.75 R15.2
  MidLayer1 w0.15: v1(17.4,18.9) 17.4,18.85 17.825,18.425 19.15,18.425 19.4,18.175 22.226,18.175 22.751,17.65 25.024,17.65 25.499,18.125 26.275,18.125 26.75,17.65 27.525,17.65 27.9,18.025 28.35,18.025 28.9,17.475 30.078,17.475 30.203,17.35 30.597,17.35 30.722,17.475 33.3,17.475 33.575,17.75 36.55,17.75 v1(36.7,17.55)
  Bottom Layer w0.15: IC6.12 17.175,18.8 v1(17.4,18.9) 17.875,18.425 18.3,18.425 18.575,18.7 18.575,22.775 16.9,24.45 v1@16.893,24.45 ; IC6.19 16.501,22.3 16.881,22.681 17.894,22.681 18.575,22 ; IC6.37 36.475,18.8 36.75,18.525 36.75,17.65 v1(36.7,17.55)
pads on no net: IC2.2 IC2.3 IC2.9 IC4.4 IC5.4 IC6.1 IC6.2 IC6.3 IC6.4 IC6.5 IC6.6 IC6.10 IC6.11 IC6.14 IC6.15 IC6.20 IC6.21 IC6.22 IC6.23 IC6.24 IC6.25 IC6.26 IC6.27 IC6.28 IC6.33 IC6.34 IC6.35 IC6.38 IC6.39 IC6.40 IC6.45 IC6.46 IC6.47 IC6.48 U2.4 U2.13 U3.4 U3.5 U3.9 U3.12 U3.13

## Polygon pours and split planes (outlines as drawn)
GND on Ground plane (split plane): 38.776,30.548 39.699,29.625 39.699,13.301 15.301,13.301 15.301,28.623 17.268,30.548

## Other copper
Top Layer:
  text "MJT Ltd" at 21.125,30.075 h0.5
  text "CWA1.3" at 25,30.075 h0.5
  text "09/11" at 28.175,30.075 h0.5

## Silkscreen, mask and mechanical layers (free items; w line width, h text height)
Mechanical 1:
  lines w0.1: 15,28.7 17.125,30.85 ; 38.85,30.85 40,29.7 ; 40,29.7 40,29.7 ; 15,13 15,30.85 40,30.85 40,13 15,13
Mechanical 2:
  lines w0.1: 15,28.7 17.15,30.85 ; 17.5,31.25 38.5,31.25 ; 38.85,30.85 40,29.7 ; 40,29.7 40,29.7 ; 15,13 15,30.85 40,30.85 40,13 15,13
  text "Edge of connector" at 23.05,31.75 h0.7
Mechanical 3:
  lines w0.1: 15,28.7 17.5,31.2 ; 38.5,31.2 40,29.7 ; 40,29.7 40,29.7 ; 15,13 15,30.85 40,30.85 40,13 15,13
Mechanical 4:
  lines w0.05: 40,29.75 40,13 15,13 15,28.75 17.1,30.85 38.9,30.85 40,29.75 ; 40,29.75 40,29.75

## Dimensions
40,30.85 to 38.5,31.25 on Mechanical 2
15,30.85 to 17.5,31.25 on Mechanical 2
15,13 to 15,30.85 on Mechanical 2
15,13 to 40,13 on Mechanical 2
38.625,31.225 to 40,30.85 on Mechanical 2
